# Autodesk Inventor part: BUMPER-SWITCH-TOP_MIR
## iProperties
Created: 2007-08
Part Number: BUMPER-SWITCH-TOP_MIR
Material: ABS Plastic
Document SubType Name: Modeling
Density: 1.06 g/cm^3
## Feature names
1. Derived Body1 [Tagging]
